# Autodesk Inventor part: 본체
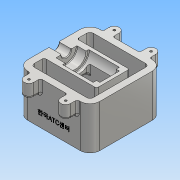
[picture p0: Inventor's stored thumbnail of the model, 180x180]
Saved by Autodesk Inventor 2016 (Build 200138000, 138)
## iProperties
Created: 2018-01
Part Number: 본체
Material: 알루미늄 6061
Document SubType Name: Modeling
Designer: Administrator
Density: 2.7 g/cm^3
Appearance: 알루미늄 - 평지
Mass: 995.263 g
Surface Area: 834.768 cm^2
Volume: 368.616 cm^3
Author: Administrator
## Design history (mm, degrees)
sketch "스케치1"
  geometry: L1 (-55, 55)-(55, 55); L2 (55, 55)-(55, -55); L3 (55, -55)-(-55, -55); L4 (-55, -55)-(-55, 55); L5 (-55, 55)-(55, -55); L6 (55, 55)-(-55, -55); 1 further point
  constraints: 12 end point, 2 midpoint, 2 parallel, 1 horizontal, 1 perpendicular
  dimensions: "d0" = 110 distance of L2.end L3.end; "d1" = 110 distance of L1.end L2.end
extrude "돌출1" new body sketch "스케치1" distance "d2" = 65; taper "d3" = 0 deg
sketch "스케치2"
  geometry: L1 (-55, 55)-(55, 55) reference; L2 (-55, -55)-(-55, 55) reference; L3 (55, 55)-(55, -55) reference; L4 (0, 0)-(55, 0); L5 (-45, 45)-(-45, 25); L6 (-45, 25)-(35, 25); L7 (35, 25)-(35, 0); L8 (-45, 45)-(45, 45); L9 (45, 45)-(45, 0); L10 (-45, -45)-(-45, -25); L11 (-45, -25)-(35, -25); L12 (35, -25)-(35, 0); L13 (-45, -45)-(45, -45); L14 (45, -45)-(45, 0)
  constraints: 22 end point, 4 symmetric about line, 3 perpendicular, 2 point on line, 1 horizontal, 1 midpoint, 1 vertical
  dimensions: "d4" = 30 distance between parallel lines of L1 L6; "d5" = 10 distance between parallel lines of L2 L5; "d6" = 10 distance between parallel lines of L3 L9; "d7" = 10 distance between parallel lines of L1 L8; "d8" = 20 distance between parallel lines of L3 L12
extrude "돌출2" cut sketch "스케치2" stored distance "d9" = 65; taper "d10" = 0 deg
sketch "스케치3"
  geometry: L1 (-55, 55)-(55, 55) reference; L2 (-55, -55)-(-55, 55) reference; L3 (-35.5, 65)-(-20.5, 65); L4 (-20.5, 65)-(-20.5, 55); L5 (-20.5, 55)-(-35.5, 55); L6 (-35.5, 55)-(-35.5, 65); L7 (-35.5, 65)-(-20.5, 55); L8 (-20.5, 65)-(-35.5, 55); L9 (0, 0)-(81.697, 0); L10 (0, 0)-(0, 41.333); L11 (20.5, 55)-(35.5, 55); L12 (35.5, 65)-(20.5, 65); L13 (35.5, 55)-(35.5, 65); L14 (35.5, 65)-(20.5, 55); L15 (20.5, 65)-(35.5, 55); L16 (20.5, 65)-(20.5, 55); L17 (20.5, -55)-(35.5, -55); L18 (35.5, -55)-(35.5, -65); L19 (20.5, -65)-(20.5, -55); L20 (35.5, -65)-(20.5, -65); L21 (35.5, -65)-(20.5, -55); L22 (20.5, -65)-(35.5, -55); L23 (-20.5, -65)-(-20.5, -55); L24 (-20.5, -55)-(-35.5, -55); L25 (-35.5, -55)-(-35.5, -65); L26 (-35.5, -65)-(-20.5, -55); L27 (-20.5, -65)-(-35.5, -55); L28 (-35.5, -65)-(-20.5, -65); A1 r 7.5 centre (-28, 65) between (-20.5, 65) and (-35.5, 65); A2 r 7.5 centre (28, 65) between (35.5, 65) and (20.5, 65); A3 r 7.5 centre (28, -65) between (20.5, -65) and (35.5, -65); A4 r 7.5 centre (-28, -65) between (-35.5, -65) and (-20.5, -65); 8 further points
  constraints: 52 end point, 21 symmetric about line, 10 midpoint, 8 point on circle, 4 centre point, 2 horizontal, 2 parallel, 1 perpendicular, 1 point on line, 1 vertical, 3 other
  dimensions: "d11" = 27 distance from line of L2 A1.centre; "d12" = 10 distance from line of L1 A1.centre; "d13" = 7.5 radius of A1
extrude "돌출3" join sketch "스케치3" distance "d14" = 20; taper "d15" = 0 deg
sketch "스케치4"
  geometry: L1 (35, -25)-(35, 25) reference; L2 (-55, -55)-(-55, 55) reference; L3 (-55, 0)-(35, 0); L4 (-55, 7.5)-(-36, 7.5); L5 (-36, 7.5)-(-36, 16); L6 (-36, 16)-(-22, 16); L7 (-22, 16)-(-22, 20); L8 (-22, 20)-(25, 20); L9 (25, 20)-(25, 15); L10 (25, 15)-(30, 15); L11 (30, 15)-(30, 0); 1 further point
  constraints: 18 end point, 7 perpendicular, 2 midpoint, 2 point on line, 1 horizontal
  dimensions: "d16" = 15 diameter of L4 L3; "d17" = 32 diameter of L6 L3; "d18" = 40 diameter of L8 L3; "d19" = 30 diameter of L10 L3; "d20" = 5 distance between parallel lines of L11 L9; "d21" = 47 distance between parallel lines of L7 L9; "d22" = 14 distance between parallel lines of L5 L7; "d23" = 19 distance between parallel lines of L2 L5
revolve "회전1" sketch "스케치4" stored, may be unused: angle "d24" = 90 deg
sketch "스케치5"
  geometry: L1 (-35, -35)-(45, -56.436); L2 (45, -56.436)-(45, -65); L3 (-45, -65)-(45, -65) reference; L4 (55, 0)-(55, -65) reference; L5 (-35, 0)-(-35, -65) reference; 1 further point
  constraints: 4 end point, 2 point on line, 1 vertical
  dimensions: "d25" = 30 distance from line of L3 L1.start; "d26" = 105 deg angle of L2 L1; "d27" = 10 distance between parallel lines of L4 L2
extrude "돌출4" cut sketch "스케치5" stored distance "d28" = 50; taper "d29" = 0 deg
sketch "스케치6"
  geometry: L1 (55, 0)-(55, -65) reference; L2 (55, -53.939)-(-20, -33.843); L3 (-20, -33.843)-(-20, 0); L4 (-25, -20)-(22, -20) reference; L5 (-20, 0)-(17, 0); L6 (17, 0)-(17, -25.757); L7 (17, -25.757)-(55, -35.939); L8 (-35, -35)-(45, -56.436) reference; L9 (22, 0)-(-25, 0) reference; 2 further points
  constraints: 10 end point, 3 perpendicular, 2 midpoint, 2 parallel, 2 point on line
  dimensions: "d30" = 5 distance between parallel lines of L8 L2; "d31" = 18 distance of L2.start L7.end; "d32" = 37 distance between parallel lines of L3 L6
extrude "돌출5" cut sketch "스케치6" stored distance "d33" = 30; taper "d34" = 0 deg
sketch "스케치7"
  geometry: L1 (0, 65)-(0, 0) reference; L2 (110, 0)-(0, 0) reference; 2 further points
  constraints: 1 other
  dimensions: "d35" = 20 distance from line of L2 point (55, 20); "d36" = 55 distance from line of L1 point (55, 20)
feature "엠보싱1" sketch "스케치7" dims "d0" = 110, "d1" = 110, "d4" = 30, "d5" = 10, "d6" = 10, "d7" = 10, "d8" = 20, "d37" = 0.5, "d38" = 0
hole "구멍1" diameter "d41" = 3.459; stored, may be unused: countersink angle "d45" = 90 deg, drill point angle "d47" = 118 deg; dims "d42" = 9, "d43" = 4, "d44" = 2, "d46" = 11, "d64" = 10, "d65" = 10
fillet "모깎기1" dims "d48" = 15
fillet "모깎기2" dims "d49" = 5
fillet "모깎기3" dims "d50" = 3
fillet "모깎기4" dims "d51" = 1
fillet "모깎기5" dims "d52" = 3
fillet "모깎기6" dims "d53" = 3
fillet "모깎기7" dims "d54" = 3
fillet "모깎기8" dims "d55" = 3
fillet "모깎기9" dims "d56" = 3
fillet "모깎기10" dims "d57" = 3
chamfer "모따기1" distance "d58" = 1; stored, may be unused: second distance "d59" = 2, angle "d60" = 45 deg
fillet "모깎기11" dims "d61" = 3
node "솔리드1"
mirror "대칭1"
mirror "대칭2"
node "작업 평면1"
